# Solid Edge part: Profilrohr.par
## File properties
Username: ahadarics
Dokumentum tartalom típus: 0
Author: ahadarics
Last saved by: ahadarics
Revision: 83
Sűrűség: 0,000 kg/m^3
Pontosság: 0,990
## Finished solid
Body 1: solid body, 6 faces, 6 edges, 0 vertices.
  Faces by surface: cone 2, cylinder 2, plane 2
  Edges by curve: circle 6
Bounding box of the edges (mm): 17.270 x 17.270 x 232.000, from (-8.635, -8.635, -211) to (8.635, 8.635, 21).
Cylindrical faces by radius (mm): R8 x1, R8.635 x1
Conical faces (half-angle, radius in mm at the cone's reference point): 15 deg R8.067 x2
Planar faces by outward normal: +z 1, -z 1
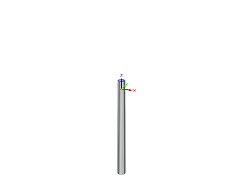
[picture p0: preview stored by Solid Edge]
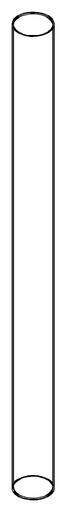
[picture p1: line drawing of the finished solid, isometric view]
